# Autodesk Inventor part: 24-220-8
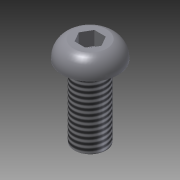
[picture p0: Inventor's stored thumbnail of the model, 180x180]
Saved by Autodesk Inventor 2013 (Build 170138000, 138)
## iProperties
Created: 2004-10
Part Number: 24-220-8
Material: Stahl (hohe Festigk., niedr. Legier.)
Document SubType Name: Modeling
Designer: Autodesk, Inc.
Manufacturer: Standard
Standards Organization: Custom
Description: SCREW, PARKER IPS, FLAT HEAD, M8X20
Catalog Web Link: http://www.parker.com/ead/cm1.asp?cmid=809
Vendor: PARKER IPS
Mass: 10.8823 g
Surface Area: 9.37524 cm^2
Volume: 1.38805 cm^3
Density: 7.84 g/cm^3
CAGE: 1LJX3
Dept. ID: Product Design
Description #2: ---
Finish #1: ---
Finish #2: ---
Material ID: ---
Project Number: ---
Author: Autodesk, Inc.
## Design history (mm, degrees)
derived "2X-YYY-ZZ IPS Screws.ipt"
body "Solid1"
tag "TaggingFeature2"
feature "Solid1::2X-YYY-ZZ IPS Screws.ipt" dims "ScaleForDerivedMember" = 10
